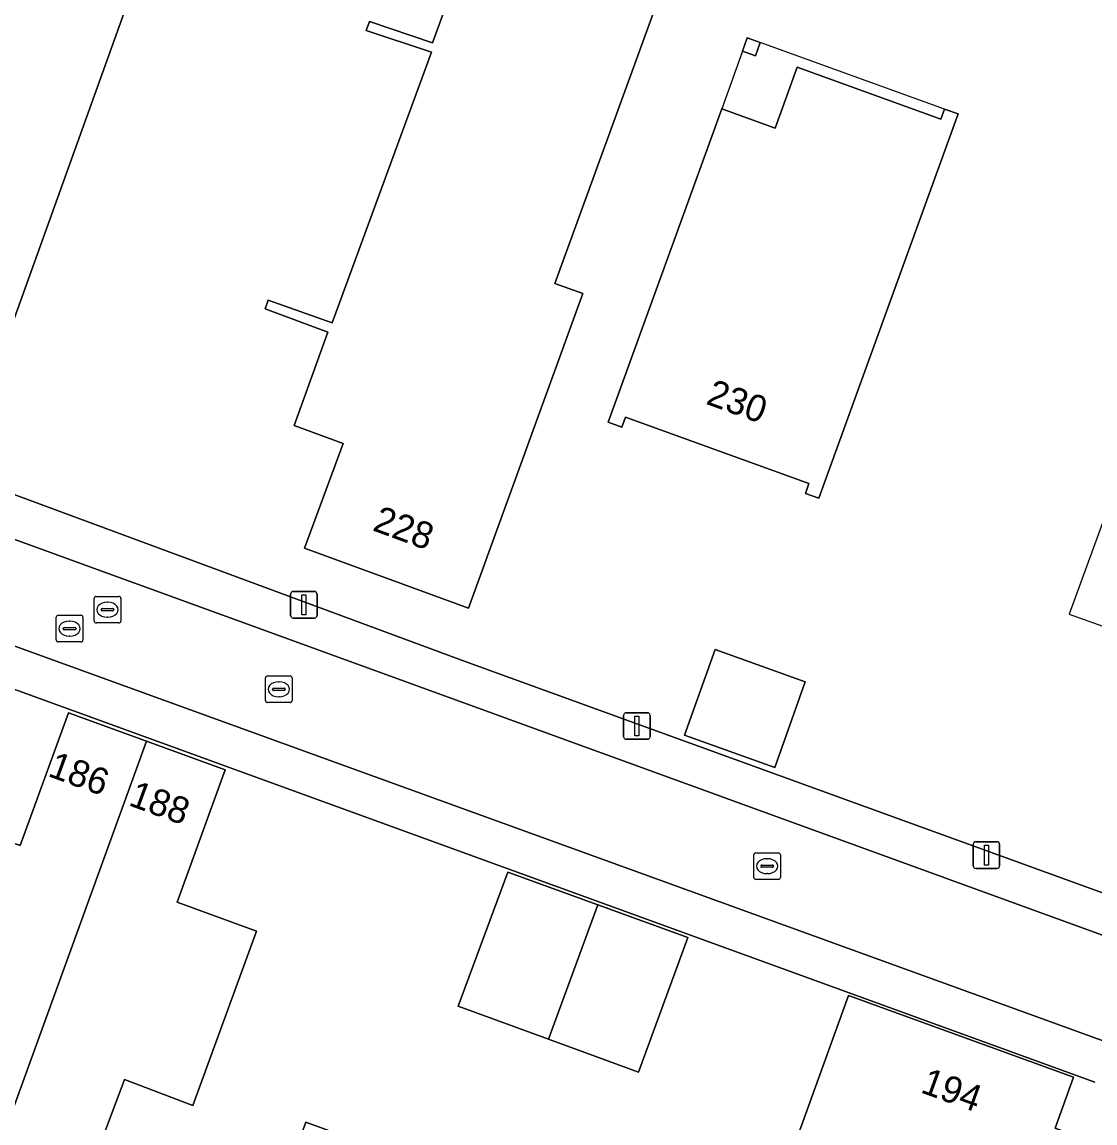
# Model space of a CAD drawing. Extents: x 155275 to 156265, y 382654 to 383635.
# Drawn here: x 155945.25 to 155985.53, y 382940.23 to 382981.58 of the extents above; entities that cross this region are included whole.
import ezdxf

# ---------------------------------------------------------------- set-up
doc = ezdxf.new("R2010")
doc.units = 0
for name, color, linetype in [('IMGEO_Erf', 7, 'Continuous'), ('IMGEO_Kolk', 7, 'Continuous'), ('IMGEO_Lichtmast', 7, 'Continuous'), ('IMGEO_Pand', 7, 'Continuous'), ('IMGEO_Pand_nummerreeks', 7, 'Continuous'), ('IMGEO_Pand_overbouw', 7, 'Continuous'), ('IMGEO_Rijbaan_lokaal_open', 7, 'Continuous'), ('IMGEO_Rioolput', 7, 'Continuous'), ('IMGEO_Voetpad_open', 7, 'Continuous')]:
    doc.layers.add(name, color=color, linetype=linetype)

msp = doc.modelspace()

# ---------------------------------------------------------------- linework, layer by layer
at = {"layer": 'IMGEO_Erf'}
for points in [[(155944.908, 382970.292), (155940.171, 382972.017), (155941.883, 382976.715), (155939.053, 382977.749), (155938.693, 382977.881), (155943.144, 382990.074), (155945.389, 382989.252), (155945.914, 382990.689), (155951.502, 382988.675)], [(155960.621, 382980.451), (155958.174, 382981.265), (155958.291, 382981.603), (155960.663, 382980.8), (155962.083, 382984.709), (155969.038, 382982.182), (155965.254, 382971.768), (155966.297, 382971.389), (155962.012, 382959.573), (155955.852, 382961.824), (155957.301, 382965.753), (155955.461, 382966.423), (155956.725, 382969.934), (155954.371, 382970.808), (155954.492, 382971.137), (155956.893, 382970.28)], [(155972.471, 382980.985), (155972.954, 382980.819), (155972.782, 382980.319), (155972.299, 382980.485)], [(155971.515, 382978.319), (155973.518, 382977.594), (155974.35, 382979.892), (155979.742, 382977.94), (155979.879, 382978.316), (155980.386, 382978.133), (155975.162, 382963.699), (155974.658, 382963.878), (155974.789, 382964.246), (155967.898, 382966.736), (155967.763, 382966.37), (155967.256, 382966.557)], [(155971.271, 382958.011), (155974.652, 382956.803), (155973.503, 382953.588), (155970.122, 382954.796)], [(155946.993, 382955.633), (155949.924, 382954.572), (155952.877, 382953.502), (155951.075, 382948.529), (155954.05, 382947.443), (155951.656, 382940.886), (155949.099, 382941.866), (155947.309, 382937.08), (155951.055, 382935.678), (155948.578, 382928.877), (155948.452, 382928.54), (155941.404, 382931.098), (155934.355, 382933.657), (155935.46, 382936.761), (155936.938, 382940.806), (155940.695, 382939.433), (155942.448, 382944.233), (155938.691, 382945.606), (155941.078, 382952.152), (155945.175, 382950.658)], [(155963.482, 382949.653), (155966.864, 382948.424), (155970.239, 382947.198), (155968.391, 382942.139), (155965.009, 382943.383), (155961.628, 382944.627)], [(155976.274, 382945.018), (155984.722, 382941.957), (155984.03, 382940.041), (155987.327, 382938.836), (155979.709, 382917.923), (155978.654, 382918.298), (155978.888, 382918.921), (155979.359, 382918.75), (155980.088, 382920.758), (155974.99, 382922.606), (155976.657, 382927.206), (155980.105, 382936.721), (155974.071, 382938.922)], [(155962.652, 382937.803), (155968.528, 382935.654), (155970.001, 382935.116), (155968.482, 382930.944), (155967.185, 382931.416), (155964.053, 382922.854), (155958.083, 382925.019), (155958.756, 382926.902), (155953.241, 382928.908), (155955.51, 382935.149), (155954.204, 382935.624), (155955.904, 382940.27)]]:
    msp.add_lwpolyline(points, close=True, dxfattribs=at)
for points in [[(155985.526, 382941.771), (155904.56, 382971.213)], [(155932.61, 382968.402), (155961.887, 382957.565), (155987.088, 382948.412)]]:
    msp.add_lwpolyline(points, dxfattribs=at)
at = {"layer": 'IMGEO_Kolk'}
for p, q in [((155954.389, 382956.097), (155954.389, 382956.949)), ((155954.464, 382957.023), (155955.316, 382957.023)), ((155954.877, 382956.803), (155954.902, 382956.803)), ((155955.39, 382956.949), (155955.39, 382956.097)), ((155954.648, 382956.517), (155954.648, 382956.529)), ((155955.086, 382956.48), (155954.688, 382956.48)), ((155954.691, 382956.566), (155955.089, 382956.566)), ((155955.132, 382956.529), (155955.132, 382956.517)), ((155955.316, 382956.023), (155954.464, 382956.023)), ((155954.9, 382956.243), (155954.875, 382956.243)), ((155972.719, 382949.453), (155972.719, 382950.305)), ((155972.794, 382950.379), (155973.646, 382950.379)), ((155973.207, 382950.159), (155973.232, 382950.159)), ((155973.72, 382950.305), (155973.72, 382949.453)), ((155972.978, 382949.873), (155972.978, 382949.885)), ((155973.416, 382949.836), (155973.018, 382949.836)), ((155973.021, 382949.922), (155973.419, 382949.922)), ((155973.462, 382949.885), (155973.462, 382949.873)), ((155973.646, 382949.379), (155972.794, 382949.379)), ((155973.23, 382949.599), (155973.205, 382949.599))]:
    msp.add_line(p, q, dxfattribs=at)
for points in [[(155954.389, 382956.097), (155954.389, 382956.949)], [(155954.464, 382957.023), (155955.316, 382957.023)], [(155955.39, 382956.949), (155955.39, 382956.097)], [(155955.316, 382956.023), (155954.464, 382956.023)], [(155972.719, 382949.453), (155972.719, 382950.305)], [(155972.794, 382950.379), (155973.646, 382950.379)], [(155973.72, 382950.305), (155973.72, 382949.453)], [(155973.646, 382949.379), (155972.794, 382949.379)]]:
    msp.add_lwpolyline(points, dxfattribs=at)
for centre, radius, start, end in [((155954.466, 382956.947), 0.0765, 91.552, 178.448), ((155954.466, 382956.947), 0.0765, 91.552, 178.448), ((155955.314, 382956.947), 0.0765, 1.552, 88.448), ((155955.314, 382956.947), 0.0765, 1.552, 88.448), ((155954.688, 382956.526), 0.0403, 85.8775, 175.7526), ((155954.685, 382956.516), 0.0366, 178.938, 274.7102), ((155955.089, 382956.523), 0.043, 264.8664, 352.4533), ((155955.093, 382956.528), 0.0386, 1.7309, 96.639), ((155954.466, 382956.099), 0.0765, 181.552, 268.448), ((155954.466, 382956.099), 0.0765, 181.552, 268.448), ((155955.314, 382956.099), 0.0765, 271.552, 358.448), ((155955.314, 382956.099), 0.0765, 271.552, 358.448), ((155972.796, 382950.303), 0.0765, 91.552, 178.448), ((155972.796, 382950.303), 0.0765, 91.552, 178.448), ((155973.644, 382950.303), 0.0765, 1.552, 88.448), ((155973.644, 382950.303), 0.0765, 1.552, 88.448), ((155973.018, 382949.882), 0.0403, 85.8775, 175.7526), ((155973.015, 382949.872), 0.0366, 178.938, 274.7102), ((155973.419, 382949.879), 0.043, 264.8664, 352.4533), ((155973.423, 382949.884), 0.0386, 1.7309, 96.639), ((155972.796, 382949.455), 0.0765, 181.552, 268.448), ((155972.796, 382949.455), 0.0765, 181.552, 268.448), ((155973.644, 382949.455), 0.0765, 271.552, 358.448), ((155973.644, 382949.455), 0.0765, 271.552, 358.448)]:
    msp.add_arc(centre, radius, start, end, dxfattribs=at)
for centre, major_axis, ratio, start_param, end_param in [((155954.876, 382956.523), (-0.387, 0.002), 0.722429, 4.712389, 7.853982), ((155954.901, 382956.523), (-0.39, 0.002), 0.717154, 1.570796, 4.712389), ((155973.206, 382949.879), (-0.387, 0.002), 0.722429, 4.712389, 7.853982), ((155973.231, 382949.879), (-0.39, 0.002), 0.717154, 1.570796, 4.712389)]:
    msp.add_ellipse(centre, major_axis=major_axis, ratio=ratio, start_param=start_param, end_param=end_param, dxfattribs=at)
at = {"layer": 'IMGEO_Lichtmast'}
for p, q in [((155955.333, 382959.299), (155955.333, 382960.099)), ((155955.333, 382960.099), (155955.333, 382959.299)), ((155955.433, 382960.199), (155956.223, 382960.199)), ((155956.223, 382960.199), (155955.433, 382960.199)), ((155956.323, 382960.099), (155956.323, 382959.299)), ((155956.323, 382959.299), (155956.323, 382960.099)), ((155956.223, 382959.199), (155955.433, 382959.199)), ((155955.433, 382959.199), (155956.223, 382959.199)), ((155967.833, 382954.743), (155967.833, 382955.543)), ((155967.833, 382955.543), (155967.833, 382954.743)), ((155967.933, 382955.643), (155968.723, 382955.643)), ((155968.723, 382955.643), (155967.933, 382955.643)), ((155968.823, 382955.543), (155968.823, 382954.743)), ((155968.823, 382954.743), (155968.823, 382955.543)), ((155968.723, 382954.643), (155967.933, 382954.643)), ((155967.933, 382954.643), (155968.723, 382954.643)), ((155980.955, 382949.895), (155980.955, 382950.695)), ((155980.955, 382950.695), (155980.955, 382949.895)), ((155981.055, 382950.795), (155981.845, 382950.795)), ((155981.845, 382950.795), (155981.055, 382950.795)), ((155981.945, 382950.695), (155981.945, 382949.895)), ((155981.945, 382949.895), (155981.945, 382950.695)), ((155981.845, 382949.795), (155981.055, 382949.795)), ((155981.055, 382949.795), (155981.845, 382949.795))]:
    msp.add_line(p, q, dxfattribs=at)
for points in [[(155955.753, 382960.074), (155955.903, 382960.074), (155955.903, 382959.324), (155955.753, 382959.324), (155955.753, 382960.074)], [(155968.253, 382955.518), (155968.403, 382955.518), (155968.403, 382954.768), (155968.253, 382954.768), (155968.253, 382955.518)], [(155981.375, 382950.67), (155981.525, 382950.67), (155981.525, 382949.92), (155981.375, 382949.92), (155981.375, 382950.67)]]:
    msp.add_lwpolyline(points, dxfattribs=at)
for centre, start, end in [((155955.433, 382960.099), 90, 180), ((155955.433, 382960.099), 90, 180), ((155956.223, 382960.099), 0, 90), ((155956.223, 382960.099), 360, 90), ((155955.433, 382959.299), 180, 270), ((155955.433, 382959.299), 180, 270), ((155956.223, 382959.299), 270, 0), ((155956.223, 382959.299), 270, 0), ((155967.933, 382955.543), 90, 180), ((155967.933, 382955.543), 90, 180), ((155968.723, 382955.543), 0, 90), ((155968.723, 382955.543), 360, 90), ((155967.933, 382954.743), 180, 270), ((155967.933, 382954.743), 180, 270), ((155968.723, 382954.743), 270, 0), ((155968.723, 382954.743), 270, 0), ((155981.055, 382950.695), 90, 180), ((155981.055, 382950.695), 90, 180), ((155981.845, 382950.695), 0, 90), ((155981.845, 382950.695), 360, 90), ((155981.055, 382949.895), 180, 270), ((155981.055, 382949.895), 180, 270), ((155981.845, 382949.895), 270, 0), ((155981.845, 382949.895), 270, 0)]:
    msp.add_arc(centre, 0.1, start, end, dxfattribs=at)
at = {"layer": 'IMGEO_Pand'}
for points in [[(155951.502, 382988.675), (155945.914, 382990.689), (155945.389, 382989.252), (155943.144, 382990.074), (155938.693, 382977.881), (155939.053, 382977.749), (155941.883, 382976.715), (155940.171, 382972.017), (155944.908, 382970.292)], [(155969.038, 382982.182), (155962.083, 382984.709), (155960.663, 382980.8), (155958.291, 382981.603), (155958.174, 382981.265), (155960.621, 382980.451), (155956.893, 382970.28), (155954.492, 382971.137), (155954.371, 382970.808), (155956.725, 382969.934), (155955.461, 382966.423), (155957.301, 382965.753), (155955.852, 382961.824), (155962.012, 382959.573), (155966.297, 382971.389), (155965.254, 382971.768)], [(155972.954, 382980.819), (155972.471, 382980.985), (155972.299, 382980.485), (155972.782, 382980.319)], [(155980.386, 382978.133), (155979.879, 382978.316), (155979.742, 382977.94), (155974.35, 382979.892), (155973.518, 382977.594), (155971.515, 382978.319), (155967.256, 382966.557), (155967.763, 382966.37), (155967.898, 382966.736), (155974.789, 382964.246), (155974.658, 382963.878), (155975.162, 382963.699)], [(155973.503, 382953.588), (155974.652, 382956.803), (155971.271, 382958.011), (155970.122, 382954.796)], [(155949.924, 382954.572), (155946.993, 382955.633), (155945.175, 382950.658), (155941.078, 382952.152), (155938.691, 382945.606), (155942.448, 382944.233), (155940.695, 382939.433), (155936.938, 382940.806), (155935.46, 382936.761), (155934.355, 382933.657), (155941.404, 382931.098)], [(155954.05, 382947.443), (155951.075, 382948.529), (155952.877, 382953.502), (155949.924, 382954.572), (155941.404, 382931.098), (155948.452, 382928.54), (155948.578, 382928.877), (155951.055, 382935.678), (155947.309, 382937.08), (155949.099, 382941.866), (155951.656, 382940.886)], [(155966.864, 382948.424), (155963.482, 382949.653), (155961.628, 382944.627), (155965.009, 382943.383)], [(155966.864, 382948.424), (155965.009, 382943.383), (155968.391, 382942.139), (155970.239, 382947.198)], [(155984.722, 382941.957), (155976.274, 382945.018), (155974.071, 382938.922), (155980.105, 382936.721), (155976.657, 382927.206), (155974.99, 382922.606), (155980.088, 382920.758), (155979.359, 382918.75), (155978.888, 382918.921), (155978.654, 382918.298), (155979.709, 382917.923), (155987.327, 382938.836), (155984.03, 382940.041)], [(155962.652, 382937.803), (155955.904, 382940.27), (155954.204, 382935.624), (155955.51, 382935.149), (155953.241, 382928.908), (155958.756, 382926.902)]]:
    msp.add_lwpolyline(points, close=True, dxfattribs=at)
at = {"layer": 'IMGEO_Pand_overbouw'}
for points in [[(155972.299, 382980.485), (155971.515, 382978.319), (155973.518, 382977.594), (155974.35, 382979.892), (155979.742, 382977.94), (155979.879, 382978.316), (155972.954, 382980.819), (155972.782, 382980.319)], [(155987.649, 382958.238), (155988.434, 382960.396), (155986.331, 382961.177), (155987.735, 382964.959), (155987.556, 382965.026), (155987.806, 382965.713), (155987.178, 382965.937), (155987.667, 382967.311), (155987.492, 382967.391), (155984.554, 382959.342)]]:
    msp.add_lwpolyline(points, close=True, dxfattribs=at)
at = {"layer": 'IMGEO_Rijbaan_lokaal_open'}
for points in [[(155905.751, 382976.414), (155901.906, 382977.812), (155900.608, 382974.241), (155904.203, 382972.936), (155904.459, 382972.843), (155986.792, 382942.972), (155986.797, 382942.97)], [(155987.503, 382942.616), (155990.616, 382941.478), (155991.912, 382945.095), (155988.117, 382946.446), (155905.751, 382976.414)]]:
    msp.add_lwpolyline(points, dxfattribs=at)
at = {"layer": 'IMGEO_Rioolput'}
for p, q in [((155947.958, 382959.086), (155947.958, 382959.938)), ((155948.033, 382960.012), (155948.885, 382960.012)), ((155948.446, 382959.792), (155948.471, 382959.792)), ((155948.959, 382959.938), (155948.959, 382959.086)), ((155946.61, 382959.3), (155947.462, 382959.3)), ((155948.217, 382959.506), (155948.217, 382959.518)), ((155948.655, 382959.469), (155948.257, 382959.469)), ((155948.26, 382959.555), (155948.658, 382959.555)), ((155948.701, 382959.518), (155948.701, 382959.506)), ((155946.535, 382958.374), (155946.535, 382959.226)), ((155946.837, 382958.843), (155947.235, 382958.843)), ((155947.023, 382959.08), (155947.048, 382959.08)), ((155947.536, 382959.226), (155947.536, 382958.374)), ((155948.885, 382959.012), (155948.033, 382959.012)), ((155948.469, 382959.232), (155948.444, 382959.232)), ((155946.794, 382958.794), (155946.794, 382958.806)), ((155947.232, 382958.757), (155946.834, 382958.757)), ((155947.046, 382958.52), (155947.021, 382958.52)), ((155947.278, 382958.806), (155947.278, 382958.794)), ((155947.462, 382958.3), (155946.61, 382958.3))]:
    msp.add_line(p, q, dxfattribs=at)
for points in [[(155947.958, 382959.086), (155947.958, 382959.938)], [(155948.033, 382960.012), (155948.885, 382960.012)], [(155948.959, 382959.938), (155948.959, 382959.086)], [(155946.61, 382959.3), (155947.462, 382959.3)], [(155946.535, 382958.374), (155946.535, 382959.226)], [(155947.536, 382959.226), (155947.536, 382958.374)], [(155948.885, 382959.012), (155948.033, 382959.012)], [(155947.462, 382958.3), (155946.61, 382958.3)]]:
    msp.add_lwpolyline(points, dxfattribs=at)
for centre, radius, start, end in [((155948.035, 382959.936), 0.0765, 91.552, 178.448), ((155948.035, 382959.936), 0.0765, 91.552, 178.448), ((155948.883, 382959.936), 0.0765, 1.552, 88.448), ((155948.883, 382959.936), 0.0765, 1.552, 88.448), ((155946.612, 382959.224), 0.0765, 91.552, 178.448), ((155946.612, 382959.224), 0.0765, 91.552, 178.448), ((155947.46, 382959.224), 0.0765, 1.552, 88.448), ((155947.46, 382959.224), 0.0765, 1.552, 88.448), ((155948.257, 382959.515), 0.0403, 85.8775, 175.7526), ((155948.254, 382959.505), 0.0366, 178.938, 274.7102), ((155948.658, 382959.512), 0.043, 264.8664, 352.4533), ((155948.662, 382959.517), 0.0386, 1.7309, 96.639), ((155946.834, 382958.803), 0.0403, 85.8775, 175.7526), ((155947.239, 382958.805), 0.0386, 1.7309, 96.639), ((155948.035, 382959.088), 0.0765, 181.552, 268.448), ((155948.035, 382959.088), 0.0765, 181.552, 268.448), ((155948.883, 382959.088), 0.0765, 271.552, 358.448), ((155948.883, 382959.088), 0.0765, 271.552, 358.448), ((155946.831, 382958.793), 0.0366, 178.938, 274.7102), ((155947.235, 382958.8), 0.043, 264.8664, 352.4533), ((155946.612, 382958.376), 0.0765, 181.552, 268.448), ((155946.612, 382958.376), 0.0765, 181.552, 268.448), ((155947.46, 382958.376), 0.0765, 271.552, 358.448), ((155947.46, 382958.376), 0.0765, 271.552, 358.448)]:
    msp.add_arc(centre, radius, start, end, dxfattribs=at)
for centre, major_axis, ratio, start_param, end_param in [((155948.445, 382959.512), (-0.387, 0.002), 0.722429, 4.712389, 7.853982), ((155948.47, 382959.512), (-0.39, 0.002), 0.717154, 1.570796, 4.712389), ((155947.022, 382958.8), (-0.387, 0.002), 0.722429, 4.712389, 7.853982), ((155947.047, 382958.8), (-0.39, 0.002), 0.717154, 1.570796, 4.712389)]:
    msp.add_ellipse(centre, major_axis=major_axis, ratio=ratio, start_param=start_param, end_param=end_param, dxfattribs=at)
at = {"layer": 'IMGEO_Voetpad_open'}
for points in [[(155905.751, 382976.414), (155988.117, 382946.446), (155988.799, 382948.185)], [(155986.115, 382941.471), (155986.792, 382942.972), (155904.459, 382972.843)], [(155904.56, 382971.213), (155985.526, 382941.771)], [(155987.088, 382948.412), (155961.887, 382957.565), (155932.61, 382968.402)]]:
    msp.add_lwpolyline(points, dxfattribs=at)

# ---------------------------------------------------------------- texts
at = {"layer": 'IMGEO_Pand_nummerreeks'}
for s, rotation, p in [('230', 340.1331, (155970.884, 382967.252)), ('228', 339.9266, (155958.369, 382962.501)), ('186', 339.8949, (155946.18, 382953.273)), ('188', 339.8949, (155949.209, 382952.177)), ('194', 340.0812, (155978.94, 382941.393))]:
    msp.add_text(s, height=1, rotation=rotation, dxfattribs=at).set_placement(p)

doc.saveas('drawing.dxf')
